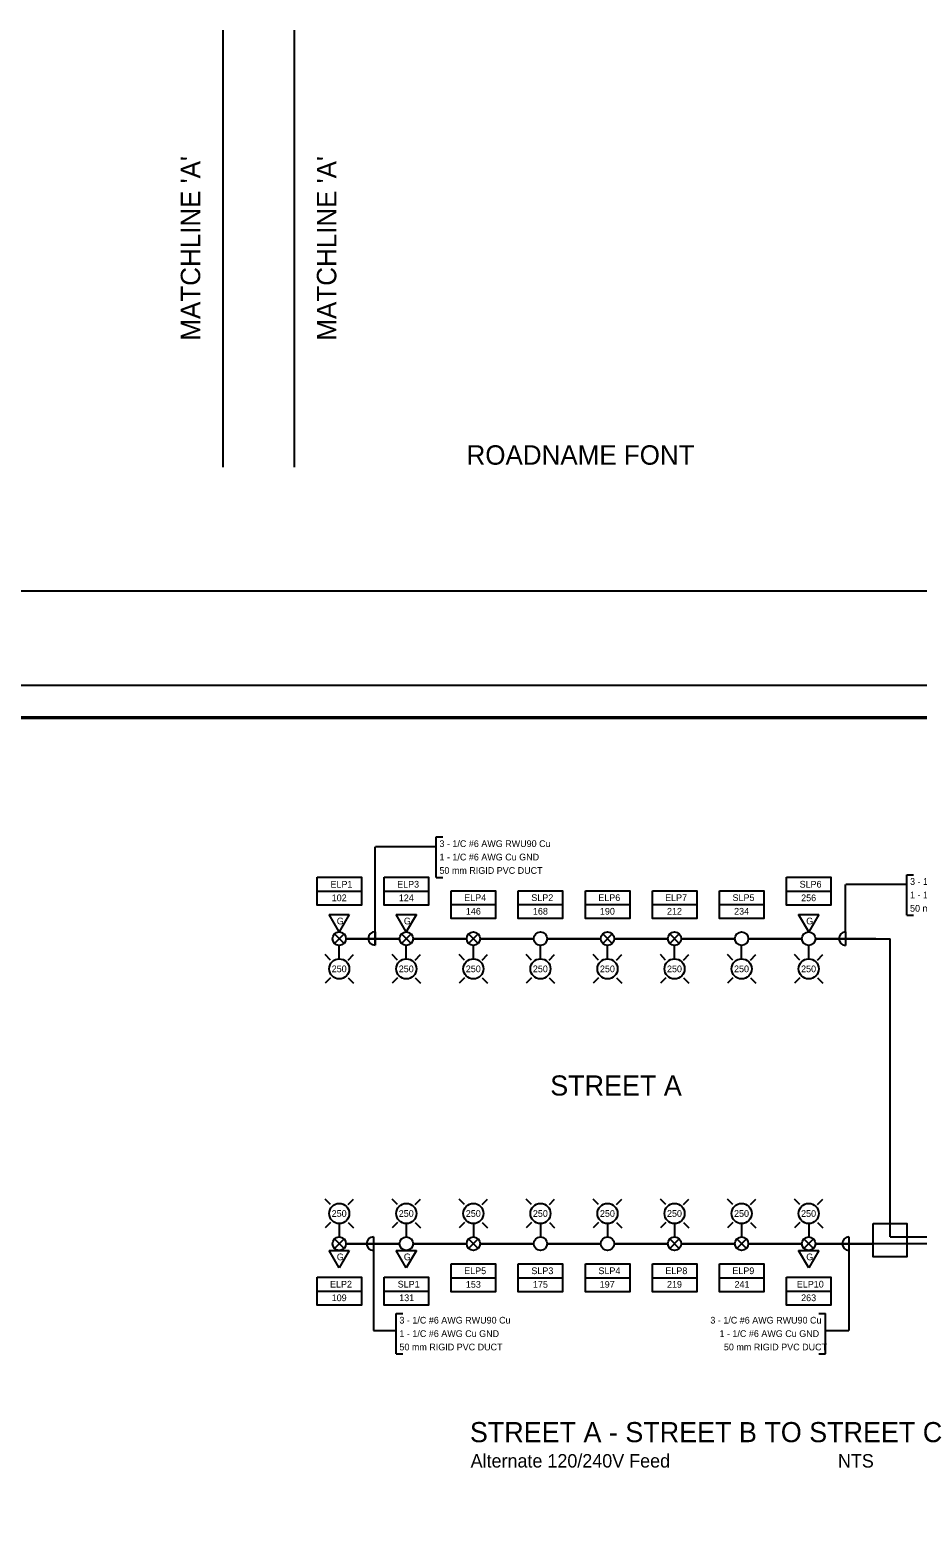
# Model space of a CAD drawing. Extents: x 602909 to 603631, y 4846273 to 4846729.
# Drawn here: x 603062.4 to 603194.8, y 4846504.5 to 4846729.3 of the extents above; entities that cross this region are included whole.
import ezdxf

# ---------------------------------------------------------------- set-up
doc = ezdxf.new("R2010")
doc.units = 0
for name, color, linetype in [('-PRINT FULLSIZE', 7, 'Continuous'), ('-PRINT HALFSIZE', 7, 'Continuous'), ('ENG_BORDER', 7, 'Continuous'), ('ENG_TITLEBLOCK', 7, 'Continuous'), ('ENG_TX_TITLEBLOCK', 7, 'Continuous'), ('SL - Wiring Diagram - Level 430', 7, 'Continuous'), ('STL_EXISTING_POLES', 7, 'Continuous'), ('STL_FIXTURES', 7, 'Continuous'), ('STL_GND_PLATE', 7, 'Continuous'), ('STL_ID', 7, 'Continuous'), ('STL_POLES', 7, 'Continuous'), ('STL_WIRING', 7, 'Continuous')]:
    doc.layers.add(name, color=color, linetype=linetype)

msp = doc.modelspace()

# ---------------------------------------------------------------- linework, layer by layer
at = {"layer": '-PRINT FULLSIZE'}
msp.add_lwpolyline([(602930, 4846340.65), (603377.03, 4846340.65), (603377.03, 4846645.65), (602930, 4846645.65)], close=True, dxfattribs=at)
at = {"layer": '-PRINT HALFSIZE'}
msp.add_lwpolyline([(602959.8, 4846631.64), (603368.72, 4846631.64), (603368.72, 4846352.64), (602959.8, 4846352.64)], close=True, dxfattribs=at)
at = {"layer": 'ENG_BORDER'}
msp.add_line((603363.72, 4846626.85), (602977.52, 4846626.85), dxfattribs=at)
msp.add_lwpolyline([(602977.52, 4846357.64), (603363.72, 4846357.64), (603363.72, 4846626.64), (602977.52, 4846626.64)], close=True, dxfattribs=at)
at = {"layer": 'ENG_TITLEBLOCK'}
for p, q in [((603091.12, 4846729.3), (603091.12, 4846664.15)), ((603101.77, 4846729.3), (603101.77, 4846664.15))]:
    msp.add_line(p, q, dxfattribs=at)
at = {"layer": 'SL - Wiring Diagram - Level 430'}
for p, q in [((603117.48, 4846593.82), (603109.48, 4846593.82)), ((603127.48, 4846593.82), (603119.48, 4846593.82)), ((603137.48, 4846593.82), (603129.48, 4846593.82)), ((603147.48, 4846593.82), (603139.48, 4846593.82)), ((603157.48, 4846593.82), (603149.48, 4846593.82)), ((603167.48, 4846593.82), (603159.48, 4846593.82)), ((603177.48, 4846593.82), (603169.48, 4846593.82)), ((603188.48, 4846593.82), (603179.48, 4846593.82)), ((603190.64, 4846550.87), (603190.64, 4846593.82)), ((603109.48, 4846548.34), (603117.48, 4846548.34)), ((603119.48, 4846548.34), (603127.48, 4846548.34)), ((603129.48, 4846548.34), (603137.48, 4846548.34)), ((603139.48, 4846548.34), (603147.48, 4846548.34)), ((603149.48, 4846548.34), (603157.48, 4846548.34)), ((603159.48, 4846548.34), (603167.48, 4846548.34)), ((603169.48, 4846548.34), (603177.48, 4846548.34)), ((603188, 4846548.34), (603179.48, 4846548.34)), ((603179.48, 4846548.34), (603188, 4846548.34))]:
    msp.add_line(p, q, dxfattribs=at)
for points in [[(603117.48, 4846593.82), (603109.48, 4846593.82)], [(603119.48, 4846593.82), (603127.48, 4846593.82)], [(603129.48, 4846593.82), (603137.48, 4846593.82)], [(603147.48, 4846593.82), (603139.48, 4846593.82)], [(603157.48, 4846593.82), (603149.48, 4846593.82)], [(603167.48, 4846593.82), (603159.48, 4846593.82)], [(603177.48, 4846593.82), (603169.48, 4846593.82)], [(603188.48, 4846593.82), (603179.48, 4846593.82)], [(603109.48, 4846548.34), (603117.48, 4846548.34)], [(603119.48, 4846548.34), (603127.48, 4846548.34)], [(603129.48, 4846548.34), (603137.48, 4846548.34)], [(603139.48, 4846548.34), (603147.48, 4846548.34)], [(603157.48, 4846548.34), (603149.48, 4846548.34)], [(603167.48, 4846548.34), (603159.48, 4846548.34)], [(603169.48, 4846548.34), (603177.48, 4846548.34)]]:
    msp.add_lwpolyline(points, dxfattribs=at)
at = {"layer": 'STL_EXISTING_POLES'}
for p, q in [((603109.19, 4846593.11), (603107.77, 4846594.52)), ((603109.19, 4846594.52), (603107.77, 4846593.11)), ((603119.19, 4846593.11), (603117.77, 4846594.52)), ((603119.19, 4846594.52), (603117.77, 4846593.11)), ((603129.19, 4846593.11), (603127.77, 4846594.52)), ((603129.19, 4846594.52), (603127.77, 4846593.11)), ((603149.19, 4846593.11), (603147.77, 4846594.52)), ((603149.19, 4846594.52), (603147.77, 4846593.11)), ((603159.19, 4846593.11), (603157.77, 4846594.52)), ((603159.19, 4846594.52), (603157.77, 4846593.11)), ((603107.77, 4846549.04), (603109.19, 4846547.63)), ((603107.77, 4846547.63), (603109.19, 4846549.04)), ((603127.77, 4846549.04), (603129.19, 4846547.63)), ((603127.77, 4846547.63), (603129.19, 4846549.04)), ((603157.77, 4846549.04), (603159.19, 4846547.63)), ((603157.77, 4846547.63), (603159.19, 4846549.04)), ((603167.77, 4846549.04), (603169.19, 4846547.63)), ((603167.77, 4846547.63), (603169.19, 4846549.04)), ((603177.77, 4846549.04), (603179.19, 4846547.63)), ((603177.77, 4846547.63), (603179.19, 4846549.04))]:
    msp.add_line(p, q, dxfattribs=at)
for centre in [(603108.48, 4846593.82), (603118.48, 4846593.82), (603128.48, 4846593.82), (603148.48, 4846593.82), (603158.48, 4846593.82), (603108.48, 4846548.34), (603128.48, 4846548.34), (603158.48, 4846548.34), (603168.48, 4846548.34), (603178.48, 4846548.34)]:
    msp.add_circle(centre, 1, dxfattribs=at)
at = {"layer": 'STL_FIXTURES'}
for p, q in [((603108.48, 4846590.82), (603108.48, 4846592.82)), ((603118.48, 4846590.82), (603118.48, 4846592.82)), ((603128.48, 4846590.82), (603128.48, 4846592.82)), ((603148.48, 4846590.82), (603148.48, 4846592.82)), ((603158.48, 4846590.82), (603158.48, 4846592.82)), ((603168.48, 4846590.82), (603168.48, 4846592.82)), ((603178.48, 4846590.82), (603178.48, 4846592.82)), ((603107.15, 4846590.64), (603106.36, 4846591.44)), ((603109.8, 4846590.64), (603110.6, 4846591.44)), ((603117.15, 4846590.64), (603116.36, 4846591.44)), ((603119.8, 4846590.64), (603120.6, 4846591.44)), ((603127.15, 4846590.64), (603126.36, 4846591.44)), ((603129.8, 4846590.64), (603130.6, 4846591.44)), ((603147.15, 4846590.64), (603146.36, 4846591.44)), ((603149.8, 4846590.64), (603150.6, 4846591.44)), ((603157.15, 4846590.64), (603156.36, 4846591.44)), ((603159.8, 4846590.64), (603160.6, 4846591.44)), ((603167.15, 4846590.64), (603166.36, 4846591.44)), ((603169.8, 4846590.64), (603170.6, 4846591.44)), ((603177.15, 4846590.64), (603176.36, 4846591.44)), ((603179.8, 4846590.64), (603180.6, 4846591.44)), ((603107.16, 4846587.99), (603106.36, 4846587.19)), ((603109.8, 4846587.99), (603110.6, 4846587.19)), ((603117.16, 4846587.99), (603116.36, 4846587.19)), ((603119.8, 4846587.99), (603120.6, 4846587.19)), ((603127.16, 4846587.99), (603126.36, 4846587.19)), ((603129.8, 4846587.99), (603130.6, 4846587.19)), ((603147.16, 4846587.99), (603146.36, 4846587.19)), ((603149.8, 4846587.99), (603150.6, 4846587.19)), ((603157.16, 4846587.99), (603156.36, 4846587.19)), ((603159.8, 4846587.99), (603160.6, 4846587.19)), ((603167.16, 4846587.99), (603166.36, 4846587.19)), ((603169.8, 4846587.99), (603170.6, 4846587.19)), ((603177.16, 4846587.99), (603176.36, 4846587.19)), ((603179.8, 4846587.99), (603180.6, 4846587.19)), ((603107.16, 4846554.16), (603106.36, 4846554.96)), ((603109.81, 4846554.16), (603110.6, 4846554.96)), ((603117.16, 4846554.16), (603116.36, 4846554.96)), ((603119.81, 4846554.16), (603120.6, 4846554.96)), ((603127.16, 4846554.16), (603126.36, 4846554.96)), ((603129.81, 4846554.16), (603130.6, 4846554.96)), ((603137.16, 4846554.16), (603136.36, 4846554.96)), ((603139.81, 4846554.16), (603140.6, 4846554.96)), ((603147.16, 4846554.16), (603146.36, 4846554.96)), ((603149.81, 4846554.16), (603150.6, 4846554.96)), ((603157.16, 4846554.16), (603156.36, 4846554.96)), ((603159.81, 4846554.16), (603160.6, 4846554.96)), ((603167.16, 4846554.16), (603166.36, 4846554.96)), ((603169.81, 4846554.16), (603170.6, 4846554.96)), ((603177.16, 4846554.16), (603176.36, 4846554.96)), ((603179.81, 4846554.16), (603180.6, 4846554.96)), ((603107.16, 4846551.51), (603106.36, 4846550.71)), ((603108.48, 4846551.34), (603108.48, 4846549.34)), ((603109.81, 4846551.51), (603110.6, 4846550.72)), ((603117.16, 4846551.51), (603116.36, 4846550.71)), ((603118.48, 4846551.34), (603118.48, 4846549.34)), ((603119.81, 4846551.51), (603120.6, 4846550.72)), ((603127.16, 4846551.51), (603126.36, 4846550.71)), ((603128.48, 4846551.34), (603128.48, 4846549.34)), ((603129.81, 4846551.51), (603130.6, 4846550.72)), ((603137.16, 4846551.51), (603136.36, 4846550.71)), ((603138.48, 4846551.34), (603138.48, 4846549.34)), ((603139.81, 4846551.51), (603140.6, 4846550.72)), ((603147.16, 4846551.51), (603146.36, 4846550.71)), ((603148.48, 4846551.34), (603148.48, 4846549.34)), ((603149.81, 4846551.51), (603150.6, 4846550.72)), ((603157.16, 4846551.51), (603156.36, 4846550.71)), ((603158.48, 4846551.34), (603158.48, 4846549.34)), ((603159.81, 4846551.51), (603160.6, 4846550.72)), ((603167.16, 4846551.51), (603166.36, 4846550.71)), ((603168.48, 4846551.34), (603168.48, 4846549.34)), ((603169.81, 4846551.51), (603170.6, 4846550.72)), ((603177.16, 4846551.51), (603176.36, 4846550.71)), ((603178.48, 4846551.34), (603178.48, 4846549.34)), ((603179.81, 4846551.51), (603180.6, 4846550.72))]:
    msp.add_line(p, q, dxfattribs=at)
for centre in [(603108.48, 4846589.32), (603118.48, 4846589.32), (603128.48, 4846589.32), (603148.48, 4846589.32), (603158.48, 4846589.32), (603168.48, 4846589.32), (603178.48, 4846589.32), (603108.48, 4846552.84), (603118.48, 4846552.84), (603128.48, 4846552.84), (603138.48, 4846552.84), (603148.48, 4846552.84), (603158.48, 4846552.84), (603168.48, 4846552.84), (603178.48, 4846552.84)]:
    msp.add_circle(centre, 1.5, dxfattribs=at)
at = {"layer": 'STL_GND_PLATE'}
for p, q in [((603108.48, 4846594.82), (603106.98, 4846597.41)), ((603106.98, 4846597.41), (603109.98, 4846597.41)), ((603109.98, 4846597.41), (603108.48, 4846594.82)), ((603118.48, 4846594.82), (603116.98, 4846597.41)), ((603116.98, 4846597.41), (603119.98, 4846597.41)), ((603119.98, 4846597.41), (603118.48, 4846594.82)), ((603178.48, 4846594.82), (603176.98, 4846597.41)), ((603176.98, 4846597.41), (603179.98, 4846597.41)), ((603179.98, 4846597.41), (603178.48, 4846594.82)), ((603108.48, 4846544.74), (603106.98, 4846547.34)), ((603106.98, 4846547.34), (603109.98, 4846547.34)), ((603109.98, 4846547.34), (603108.48, 4846544.74)), ((603118.48, 4846544.74), (603116.98, 4846547.34)), ((603116.98, 4846547.34), (603119.98, 4846547.34)), ((603119.98, 4846547.34), (603118.48, 4846544.74)), ((603178.48, 4846544.74), (603176.98, 4846547.34)), ((603176.98, 4846547.34), (603179.98, 4846547.34)), ((603179.98, 4846547.34), (603178.48, 4846544.74))]:
    msp.add_line(p, q, dxfattribs=at)
at = {"layer": 'STL_ID'}
for p, q in [((603105.18, 4846600.9), (603111.79, 4846600.9)), ((603115.18, 4846600.9), (603121.79, 4846600.9)), ((603175.18, 4846600.9), (603181.79, 4846600.9)), ((603125.18, 4846598.9), (603131.79, 4846598.9)), ((603135.18, 4846598.9), (603141.79, 4846598.9)), ((603145.18, 4846598.9), (603151.79, 4846598.9)), ((603155.18, 4846598.9), (603161.79, 4846598.9)), ((603165.18, 4846598.9), (603171.79, 4846598.9)), ((603125.18, 4846543.26), (603131.79, 4846543.26)), ((603135.18, 4846543.26), (603141.79, 4846543.26)), ((603145.18, 4846543.26), (603151.79, 4846543.26)), ((603155.18, 4846543.26), (603161.79, 4846543.26)), ((603165.18, 4846543.26), (603171.79, 4846543.26)), ((603105.18, 4846541.26), (603111.79, 4846541.26)), ((603115.18, 4846541.26), (603121.79, 4846541.26)), ((603175.18, 4846541.26), (603181.79, 4846541.26))]:
    msp.add_line(p, q, dxfattribs=at)
for points in [[(603105.18, 4846602.98), (603111.79, 4846602.98), (603111.79, 4846598.82), (603105.18, 4846598.82)], [(603115.18, 4846602.98), (603121.79, 4846602.98), (603121.79, 4846598.82), (603115.18, 4846598.82)], [(603175.18, 4846602.98), (603181.79, 4846602.98), (603181.79, 4846598.82), (603175.18, 4846598.82)], [(603125.18, 4846600.98), (603131.79, 4846600.98), (603131.79, 4846596.82), (603125.18, 4846596.82)], [(603135.18, 4846600.98), (603141.79, 4846600.98), (603141.79, 4846596.82), (603135.18, 4846596.82)], [(603145.18, 4846600.98), (603151.79, 4846600.98), (603151.79, 4846596.82), (603145.18, 4846596.82)], [(603155.18, 4846600.98), (603161.79, 4846600.98), (603161.79, 4846596.82), (603155.18, 4846596.82)], [(603165.18, 4846600.98), (603171.79, 4846600.98), (603171.79, 4846596.82), (603165.18, 4846596.82)], [(603105.18, 4846543.34), (603111.79, 4846543.34), (603111.79, 4846539.17), (603105.18, 4846539.17)], [(603115.18, 4846543.34), (603121.79, 4846543.34), (603121.79, 4846539.17), (603115.18, 4846539.17)], [(603125.18, 4846545.34), (603131.79, 4846545.34), (603131.79, 4846541.17), (603125.18, 4846541.17)], [(603135.18, 4846545.34), (603141.79, 4846545.34), (603141.79, 4846541.17), (603135.18, 4846541.17)], [(603145.18, 4846545.34), (603151.79, 4846545.34), (603151.79, 4846541.17), (603145.18, 4846541.17)], [(603155.18, 4846545.34), (603161.79, 4846545.34), (603161.79, 4846541.17), (603155.18, 4846541.17)], [(603165.18, 4846545.34), (603171.79, 4846545.34), (603171.79, 4846541.17), (603165.18, 4846541.17)], [(603175.18, 4846543.34), (603181.79, 4846543.34), (603181.79, 4846539.17), (603175.18, 4846539.17)]]:
    msp.add_lwpolyline(points, close=True, dxfattribs=at)
at = {"layer": 'STL_POLES'}
for p, q in [((603138.48, 4846590.82), (603138.48, 4846592.82)), ((603137.15, 4846590.64), (603136.36, 4846591.44)), ((603139.8, 4846590.64), (603140.6, 4846591.44)), ((603137.16, 4846587.99), (603136.36, 4846587.19)), ((603139.8, 4846587.99), (603140.6, 4846587.19))]:
    msp.add_line(p, q, dxfattribs=at)
for centre, radius in [((603138.48, 4846593.82), 1), ((603168.48, 4846593.82), 1), ((603178.48, 4846593.82), 1), ((603138.48, 4846589.32), 1.5), ((603118.48, 4846548.34), 1), ((603138.48, 4846548.34), 1), ((603148.48, 4846548.34), 1)]:
    msp.add_circle(centre, radius, dxfattribs=at)
at = {"layer": 'STL_WIRING'}
for p, q in [((603122.92, 4846608.99), (603123.92, 4846608.99)), ((603113.81, 4846592.86), (603113.81, 4846607.53)), ((603122.92, 4846607.53), (603113.86, 4846607.53)), ((603122.92, 4846602.95), (603123.92, 4846602.95)), ((603183.98, 4846594.82), (603183.98, 4846601.89)), ((603193.1, 4846601.89), (603184.04, 4846601.89)), ((603193.1, 4846603.35), (603194.1, 4846603.35)), ((603193.1, 4846597.31), (603194.1, 4846597.31)), ((603109.48, 4846593.82), (603117.48, 4846593.82)), ((603113.81, 4846594.86), (603113.81, 4846592.86)), ((603119.48, 4846593.82), (603127.48, 4846593.82)), ((603129.48, 4846593.82), (603137.48, 4846593.82)), ((603139.48, 4846593.82), (603147.48, 4846593.82)), ((603149.48, 4846593.82), (603157.48, 4846593.82)), ((603159.48, 4846593.82), (603167.48, 4846593.82)), ((603169.48, 4846593.82), (603177.48, 4846593.82)), ((603179.48, 4846593.82), (603190.64, 4846593.82)), ((603183.98, 4846594.82), (603183.98, 4846592.82)), ((603190.64, 4846549.34), (603190.64, 4846593.82)), ((603117.48, 4846548.34), (603109.48, 4846548.34)), ((603113.56, 4846549.34), (603113.56, 4846547.34)), ((603127.48, 4846548.34), (603119.48, 4846548.34)), ((603137.48, 4846548.34), (603129.48, 4846548.34)), ((603147.48, 4846548.34), (603139.48, 4846548.34)), ((603157.48, 4846548.34), (603149.48, 4846548.34)), ((603167.48, 4846548.34), (603159.48, 4846548.34)), ((603177.48, 4846548.34), (603169.48, 4846548.34)), ((603188, 4846548.34), (603179.48, 4846548.34)), ((603184.48, 4846549.34), (603184.48, 4846547.34)), ((603208.3, 4846548.34), (603186.78, 4846548.34)), ((603190.64, 4846549.34), (603208.3, 4846549.34)), ((603113.56, 4846547.34), (603113.56, 4846535.41)), ((603184.48, 4846547.34), (603184.48, 4846535.41)), ((603116.95, 4846537.93), (603117.95, 4846537.93)), ((603179.98, 4846537.93), (603180.98, 4846537.93)), ((603113.56, 4846535.41), (603116.95, 4846535.41)), ((603180.98, 4846535.41), (603184.48, 4846535.41)), ((603116.95, 4846531.9), (603117.95, 4846531.9)), ((603179.98, 4846531.9), (603180.98, 4846531.9))]:
    msp.add_line(p, q, dxfattribs=at)
for points in [[(603122.92, 4846602.95), (603122.92, 4846608.99)], [(603193.1, 4846597.31), (603193.1, 4846603.35)], [(603116.95, 4846531.9), (603116.95, 4846537.93)], [(603180.98, 4846531.9), (603180.98, 4846537.93)]]:
    msp.add_lwpolyline(points, dxfattribs=at)
msp.add_lwpolyline([(603188.12, 4846551.37), (603193.12, 4846551.37), (603193.12, 4846546.37), (603188.12, 4846546.37)], close=True, dxfattribs=at)
for centre in [(603113.81, 4846593.86), (603183.98, 4846593.82), (603113.56, 4846548.34), (603184.48, 4846548.34)]:
    msp.add_arc(centre, 1, 90, 270, dxfattribs=at)

# ---------------------------------------------------------------- texts
at = {"layer": 'ENG_TX_TITLEBLOCK'}
for p in [(603087.74, 4846683), (603108.04, 4846683)]:
    msp.add_text("MATCHLINE 'A'", height=2.8965, rotation=89.9999, dxfattribs=at).set_placement(p)
for s, height, p in [('ROADNAME FONT', 2.8965, (603127.46, 4846664.5)), ('STREET A', 3, (603139.94, 4846570.43)), ('STREET A - STREET B TO STREET C', 3, (603127.96, 4846518.74)), ('Alternate 120/240V Feed', 2, (603128.07, 4846514.96)), ('NTS', 2, (603182.84, 4846514.96))]:
    msp.add_text(s, height=height, dxfattribs=at).set_placement(p)
at = {"layer": 'STL_GND_PLATE'}
for p in [(603108.11, 4846595.95), (603118.11, 4846595.95), (603178.11, 4846595.95), (603108.11, 4846545.87), (603118.11, 4846545.87), (603178.11, 4846545.87)]:
    msp.add_text('G', height=1, rotation=359.9999, dxfattribs=at).set_placement(p)
at = {"layer": 'STL_ID'}
for s, p in [('3 - 1/C #6 AWG RWU90 Cu', (603123.42, 4846607.49)), ('1 - 1/C #6 AWG Cu GND', (603123.42, 4846605.49)), ('50 mm RIGID PVC DUCT', (603123.42, 4846603.49)), ('ELP1', (603107.17, 4846601.44)), ('ELP3', (603117.11, 4846601.44)), ('SLP6', (603177.13, 4846601.44)), ('3 - 1/C #6 AWG RWU90 Cu', (603193.6, 4846601.85)), ('102', (603107.35, 4846599.41)), ('124', (603117.36, 4846599.41)), ('ELP4', (603127.11, 4846599.44)), ('SLP2', (603137.12, 4846599.44)), ('ELP6', (603147.11, 4846599.44)), ('ELP7', (603157.07, 4846599.44)), ('SLP5', (603167.13, 4846599.44)), ('256', (603177.36, 4846599.41)), ('1 - 1/C #6 AWG Cu GND', (603193.6, 4846599.85)), ('146', (603127.36, 4846597.41)), ('168', (603137.36, 4846597.41)), ('190', (603147.35, 4846597.41)), ('212', (603157.35, 4846597.41)), ('234', (603167.36, 4846597.41)), ('50 mm RIGID PVC DUCT', (603193.6, 4846597.85)), ('250', (603107.35, 4846588.82)), ('250', (603117.35, 4846588.82)), ('250', (603127.35, 4846588.82)), ('250', (603137.35, 4846588.82)), ('250', (603147.35, 4846588.82)), ('250', (603157.35, 4846588.82)), ('250', (603167.35, 4846588.82)), ('250', (603177.35, 4846588.82)), ('250', (603107.35, 4846552.34)), ('250', (603117.35, 4846552.34)), ('250', (603127.35, 4846552.34)), ('250', (603137.35, 4846552.34)), ('250', (603147.35, 4846552.34)), ('250', (603157.35, 4846552.34)), ('250', (603167.35, 4846552.34)), ('250', (603177.35, 4846552.34)), ('ELP5', (603127.11, 4846543.8)), ('SLP3', (603137.13, 4846543.8)), ('SLP4', (603147.13, 4846543.8)), ('ELP8', (603157.11, 4846543.8)), ('ELP9', (603167.1, 4846543.8)), ('ELP2', (603107.1, 4846541.8)), ('SLP1', (603117.19, 4846541.8)), ('153', (603127.36, 4846541.77)), ('175', (603137.36, 4846541.77)), ('197', (603147.32, 4846541.77)), ('219', (603157.35, 4846541.77)), ('241', (603167.42, 4846541.77)), ('ELP10', (603176.71, 4846541.8)), ('109', (603107.35, 4846539.77)), ('131', (603117.42, 4846539.77)), ('263', (603177.36, 4846539.77)), ('3 - 1/C #6 AWG RWU90 Cu', (603117.45, 4846536.43)), ('3 - 1/C #6 AWG RWU90 Cu', (603163.82, 4846536.43)), ('1 - 1/C #6 AWG Cu GND', (603117.45, 4846534.43)), ('1 - 1/C #6 AWG Cu GND', (603165.18, 4846534.43)), ('50 mm RIGID PVC DUCT', (603117.45, 4846532.43)), ('50 mm RIGID PVC DUCT', (603165.84, 4846532.43))]:
    msp.add_text(s, height=1, dxfattribs=at).set_placement(p)

doc.saveas('drawing.dxf')
